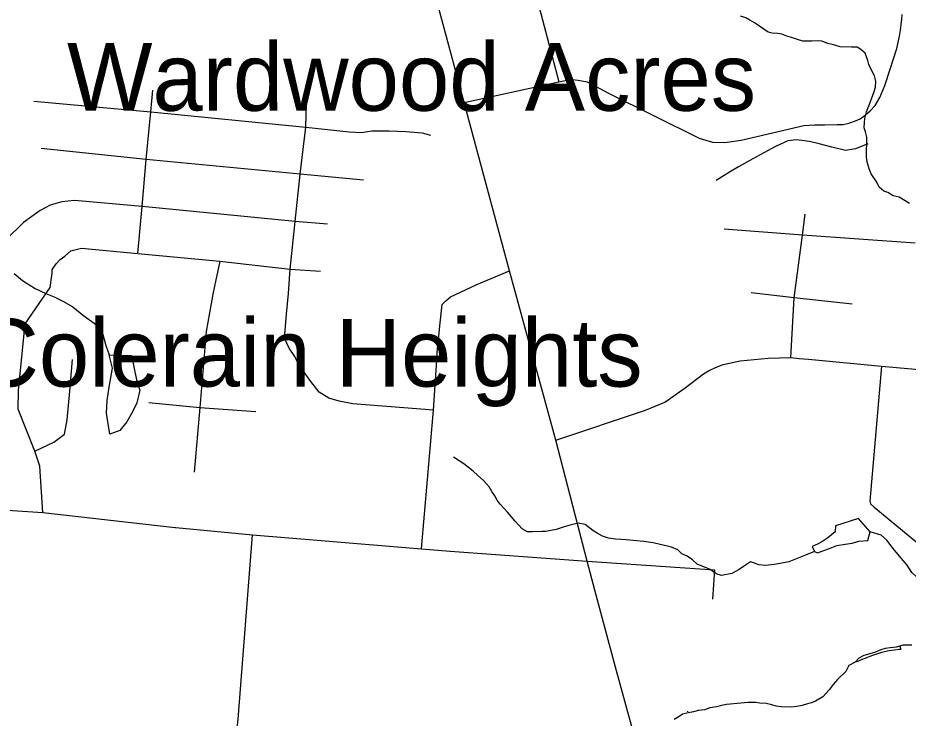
# Model space of a CAD drawing. Extents: x 0 to 34, y 0 to 22.
# Drawn here: x 3.515 to 4.554, y 16.285 to 17.102 of the extents above; entities that cross this region are included whole.
import ezdxf

# ---------------------------------------------------------------- set-up
doc = ezdxf.new("R2010")
doc.units = 0
for name, color, linetype in [('GM_X_County_Road', 7, 'Continuous'), ('GM_X_Minor_Lake', 7, 'Continuous'), ('GM_X_Minor_River', 7, 'Continuous'), ('GM_X_Township_Subdivision', 7, 'Continuous'), ('GM_X_Unincorporated_Text', 7, 'Continuous'), ('GM_X_US_Route', 7, 'Continuous')]:
    doc.layers.add(name, color=color, linetype=linetype)

msp = doc.modelspace()

# ---------------------------------------------------------------- linework, layer by layer
at = {"layer": 'GM_X_County_Road'}
for points in [[(4.1431, 16.6089), (4.2477, 16.644), (4.27, 16.6535), (4.294, 16.6701), (4.3151, 16.6862), (4.3212, 16.6898), (4.3294, 16.6938), (4.3383, 16.6974), (4.3582, 16.7015), (4.3907, 16.7048), (4.417, 16.7053), (4.427, 16.7043), (4.4376, 16.7033), (4.5229, 16.6954), (4.6194, 16.6869)], [(3.0077, 16.6072), (3.0199, 16.6034), (3.2263, 16.5685), (3.2928, 16.5595), (3.3237, 16.5541), (3.3826, 16.5464), (3.4363, 16.5348), (3.4732, 16.5304), (3.5089, 16.527), (3.5443, 16.5245), (3.6987, 16.5072), (3.6996, 16.5071)], [(3.6996, 16.5071), (3.7888, 16.4987), (3.8689, 16.4921)], [(3.6274, 15.5008), (3.6334, 15.5983), (3.6428, 15.6844), (3.6442, 15.6947), (3.6526, 15.7123), (3.6907, 15.7752), (3.6948, 15.7884), (3.6964, 15.8066), (3.7002, 15.8416), (3.7057, 15.8918), (3.7083, 15.9035), (3.7269, 15.9403), (3.7414, 15.9828), (3.7462, 16.0207), (3.7514, 16.0744), (3.7681, 16.2443), (3.7721, 16.2837), (3.7888, 16.4987)], [(3.8689, 16.4921), (3.869, 16.4921), (3.986, 16.4824), (4.0195, 16.4796), (4.1794, 16.4679)]]:
    msp.add_lwpolyline(points, dxfattribs=at)
at = {"layer": 'GM_X_Minor_Lake'}
for points in [[(3.6224, 16.6158), (3.6187, 16.6406), (3.6194, 16.6554), (3.6216, 16.6709), (3.6255, 16.6928), (3.6218, 16.7084)], [(3.6218, 16.7084), (3.6479, 16.7079), (3.6534, 16.6793), (3.6573, 16.6674), (3.6539, 16.6527), (3.6487, 16.6422), (3.6424, 16.6302), (3.6342, 16.6201), (3.6223, 16.6158)], [(4.5098, 16.5021), (4.4963, 16.5177), (4.4692, 16.5092), (4.469, 16.502), (4.4605, 16.495), (4.4532, 16.4906), (4.4482, 16.4877), (4.442, 16.4848), (4.4446, 16.479), (4.4483, 16.4774), (4.4613, 16.4821), (4.4709, 16.486), (4.4805, 16.4877), (4.4888, 16.489), (4.4965, 16.4912)], [(4.4965, 16.4912), (4.507, 16.4921), (4.5098, 16.5021)]]:
    msp.add_lwpolyline(points, dxfattribs=at)
at = {"layer": 'GM_X_Minor_River'}
for points in [[(4.5556, 16.8851), (4.5436, 16.8923), (4.5364, 16.8941), (4.5304, 16.8977), (4.5255, 16.8993), (4.5203, 16.904), (4.5175, 16.9098), (4.5109, 16.9195), (4.5084, 16.9253), (4.5063, 16.9337), (4.5053, 16.9391), (4.506, 16.9623), (4.5042, 16.9685), (4.5028, 16.9731), (4.503, 16.9795), (4.5035, 16.9841), (4.5056, 16.992), (4.5081, 16.9988), (4.5114, 17.0071), (4.5143, 17.0158), (4.5159, 17.0207), (4.5165, 17.0279), (4.5147, 17.034), (4.5104, 17.0422), (4.5083, 17.0472), (4.5072, 17.0518), (4.504, 17.0602), (4.4988, 17.0646), (4.4944, 17.0674), (4.4879, 17.0672), (4.4746, 17.0679), (4.467, 17.07), (4.4602, 17.0717), (4.4535, 17.0742), (4.4482, 17.0747), (4.4417, 17.0745), (4.4356, 17.0743), (4.431, 17.0745), (4.425, 17.0762), (4.4178, 17.0786), (4.4126, 17.0803), (4.4065, 17.0824), (4.402, 17.0833), (4.3952, 17.0838), (4.3906, 17.0847), (4.3806, 17.0919), (4.3746, 17.0958), (4.3693, 17.0987), (4.3648, 17.1014), (4.3584, 17.1035)], [(4.5057, 16.9543), (4.5072, 16.9546), (4.4926, 16.9489), (4.4808, 16.9469), (4.4649, 16.9507), (4.4502, 16.9548), (4.4388, 16.9574), (4.4237, 16.9593), (4.4138, 16.958), (4.3999, 16.9519), (4.3899, 16.9464), (4.373, 16.9373), (4.356, 16.9278), (4.3456, 16.9216), (4.3302, 16.9117)], [(3.5109, 16.8032), (3.5206, 16.7953), (3.5352, 16.7859), (3.5476, 16.7802), (3.5574, 16.7762), (3.5675, 16.771), (3.5791, 16.7646), (3.5922, 16.754), (3.6041, 16.7454), (3.6141, 16.7322), (3.6176, 16.7196), (3.6218, 16.7084)], [(4.4446, 16.479), (4.4342, 16.475), (4.4149, 16.4671), (4.4023, 16.4648), (4.3977, 16.4638), (4.3878, 16.4629), (4.3799, 16.4635), (4.3746, 16.4656), (4.3701, 16.4669), (4.3619, 16.4618), (4.3569, 16.4581), (4.3484, 16.4534), (4.3362, 16.4511), (4.3301, 16.4531), (4.323, 16.4583), (4.3174, 16.4603), (4.3125, 16.4624), (4.308, 16.4644), (4.3024, 16.4695), (4.2961, 16.4735), (4.2901, 16.4763), (4.2853, 16.481), (4.2777, 16.4843), (4.2732, 16.4852), (4.2645, 16.4873), (4.2566, 16.4891), (4.2456, 16.4909), (4.2251, 16.4926), (4.2126, 16.4934), (4.2042, 16.4947), (4.1975, 16.4972), (4.1911, 16.5004), (4.1862, 16.5036), (4.1773, 16.5107), (4.169, 16.5121), (4.1579, 16.5094), (4.1514, 16.5076), (4.1433, 16.5048), (4.1372, 16.5035), (4.1314, 16.5025), (4.1269, 16.5026), (4.1158, 16.5022), (4.1097, 16.5019), (4.1038, 16.5055), (4.0953, 16.5145), (4.0908, 16.52), (4.0864, 16.5251), (4.0779, 16.5344), (4.0743, 16.5391), (4.0717, 16.5441), (4.0684, 16.5492), (4.0652, 16.5546), (4.0585, 16.562), (4.0518, 16.5679), (4.0466, 16.573), (4.0411, 16.577), (4.0355, 16.5813), (4.0302, 16.5849), (4.0235, 16.5893)], [(4.6349, 16.4612), (4.6183, 16.4634), (4.6087, 16.4591), (4.5991, 16.4555), (4.5925, 16.4527), (4.5845, 16.4506), (4.576, 16.4482), (4.5692, 16.4495), (4.5635, 16.45), (4.5583, 16.4548), (4.5529, 16.4633), (4.5462, 16.4711), (4.5422, 16.4762), (4.5367, 16.4828), (4.5326, 16.4878), (4.5293, 16.4925), (4.5226, 16.498), (4.5097, 16.5022)], [(4.5443, 16.3688), (4.5455, 16.365), (4.543, 16.3647), (4.5382, 16.3641), (4.532, 16.3633), (4.5263, 16.3621), (4.5229, 16.3612), (4.5171, 16.3593), (4.5125, 16.3579), (4.5092, 16.3567), (4.5056, 16.3552), (4.5027, 16.354), (4.5012, 16.3536), (4.4985, 16.3524), (4.496, 16.3514), (4.4935, 16.3505), (4.4921, 16.3499)], [(4.54, 16.3677), (4.5331, 16.3667), (4.5274, 16.3661), (4.5221, 16.3644), (4.5147, 16.3612), (4.5025, 16.3577), (4.4967, 16.3548), (4.4921, 16.3499)], [(4.5443, 16.3688), (4.54, 16.3677)], [(4.5583, 16.3698), (4.553, 16.37), (4.5477, 16.3698), (4.5443, 16.3688)], [(4.4921, 16.3499), (4.4847, 16.346), (4.4814, 16.3392), (4.4717, 16.33), (4.4666, 16.324), (4.4618, 16.3177), (4.4544, 16.3095), (4.4459, 16.3044), (4.4413, 16.3027), (4.4367, 16.3013), (4.4305, 16.2995), (4.424, 16.2982), (4.4183, 16.2976), (4.4058, 16.2979), (4.4001, 16.2989), (4.3948, 16.3001), (4.3884, 16.3018), (4.3808, 16.3024), (4.3759, 16.303), (4.3675, 16.3032), (4.3587, 16.3023), (4.342, 16.3005), (4.3362, 16.2995), (4.3305, 16.2978), (4.3228, 16.2968), (4.3163, 16.2943), (4.3095, 16.2938), (4.3037, 16.292), (4.2957, 16.2907), (4.2913, 16.2894)], [(4.2965, 16.293), (4.2966, 16.2923)], [(4.2917, 16.2899), (4.2868, 16.2868), (4.281, 16.2831)]]:
    msp.add_lwpolyline(points, dxfattribs=at)
at = {"layer": 'GM_X_Township_Subdivision'}
for points in [[(4.2504, 17.246), (4.2399, 17.2463), (4.2209, 17.2479), (4.2, 17.2504), (4.1444, 17.2619), (4.1342, 17.2617), (4.1233, 17.2587), (4.1133, 17.2519), (4.1072, 17.2448), (4.1016, 17.2378), (4.098, 17.2281), (4.0972, 17.2166), (4.1007, 17.2009), (4.1059, 17.1806), (4.1093, 17.1652), (4.1138, 17.1512), (4.1464, 17.0268)], [(4.5267, 17.0228), (4.5332, 17.0419), (4.5407, 17.066), (4.5441, 17.0801), (4.5451, 17.0873), (4.5458, 17.0934), (4.5465, 17.0999), (4.5469, 17.1055)], [(4.0359, 17.0028), (4.1464, 17.0268), (4.1519, 17.0281)], [(4.1519, 17.0281), (4.1588, 17.0296), (4.162, 17.0296), (4.1688, 17.0289), (4.1794, 17.0268), (4.1835, 17.0251), (4.2044, 17.0136), (4.31, 16.9611), (4.3256, 16.9565), (4.3403, 16.9561), (4.3591, 16.9591), (4.4325, 16.9761), (4.4446, 16.9767), (4.4568, 16.9769), (4.4711, 16.9771), (4.4782, 16.9773), (4.4849, 16.9788), (4.4925, 16.9813), (4.498, 16.9837), (4.5039, 16.9882), (4.5096, 16.993), (4.5154, 16.9992), (4.5212, 17.0085), (4.5267, 17.0228)], [(3.6551, 16.8268), (3.6602, 16.8815), (3.6648, 16.9362), (3.6704, 16.9918), (3.6728, 17.0173)], [(3.5337, 17.0043), (3.6704, 16.9918), (3.851, 16.9739), (3.9019, 16.9687), (3.9161, 16.9677), (3.9282, 16.9699), (3.9484, 16.9699), (3.968, 16.969), (3.9869, 16.9674), (3.9965, 16.9649)], [(4.0003, 16.6438), (3.9059, 16.6515), (3.8901, 16.6543), (3.878, 16.658), (3.8668, 16.6649), (3.8569, 16.6776), (3.8426, 16.6978), (3.8383, 16.7064), (3.8317, 16.7164), (3.8261, 16.7279), (3.8274, 16.7415), (3.8286, 16.7561), (3.8308, 16.78), (3.8327, 16.8085), (3.8386, 16.8639), (3.8445, 16.9193), (3.851, 16.9739), (3.8519, 17.0009)], [(3.9186, 16.9122), (3.8445, 16.9193), (3.6648, 16.9362), (3.5425, 16.9491)], [(3.8766, 16.8608), (3.8386, 16.8639), (3.6602, 16.8815), (3.5812, 16.8884), (3.5665, 16.887), (3.553, 16.8832), (3.541, 16.877), (3.5216, 16.8628), (3.4605, 16.8035), (3.4221, 16.7604), (3.3897, 16.7285), (3.3838, 16.7214), (3.3793, 16.711), (3.3779, 16.6956), (3.3748, 16.6696), (3.3712, 16.6447), (3.371, 16.6339), (3.3731, 16.6233), (3.3815, 16.607), (3.3861, 16.5965), (3.388, 16.5857), (3.3826, 16.5464)], [(4.417, 16.7053), (4.421, 16.7752), (4.4308, 16.8481), (4.434, 16.8724)], [(4.5621, 16.8386), (4.4308, 16.8481), (4.3393, 16.855)], [(3.5546, 16.8011), (3.555, 16.8037), (3.5553, 16.8076), (3.5562, 16.8098), (3.5597, 16.8147), (3.5644, 16.8199), (3.5698, 16.8235), (3.5769, 16.8299), (3.5893, 16.833), (3.6551, 16.8268), (3.7507, 16.8176), (3.8327, 16.8085), (3.8684, 16.8061)], [(3.7507, 16.8176), (3.7446, 16.7885)], [(4.0044, 16.7081), (4.0046, 16.7116), (4.0079, 16.7459), (4.0104, 16.7671), (4.0145, 16.7716), (4.02, 16.7762), (4.0507, 16.7906), (4.0889, 16.8066)], [(3.5443, 16.5245), (3.5409, 16.5785), (3.535, 16.5962), (3.5154, 16.6452), (3.5157, 16.6673), (3.5235, 16.7448), (3.5527, 16.787), (3.5546, 16.8011)], [(3.7446, 16.7885), (3.7426, 16.7791), (3.7348, 16.7357), (3.7274, 16.6472), (3.7209, 16.5715)], [(4.4889, 16.7676), (4.421, 16.7752), (4.3708, 16.7808)], [(3.986, 16.4824), (4.0003, 16.6438), (4.0044, 16.7081)], [(3.535, 16.5962), (3.557, 16.6066), (3.5697, 16.6161), (3.5728, 16.6328), (3.5756, 16.6663), (3.5787, 16.703)], [(4.5229, 16.6954), (4.5093, 16.5377), (4.51, 16.5346), (4.514, 16.5314), (4.5654, 16.4888), (4.5695, 16.486), (4.5759, 16.4851), (4.6004, 16.488), (4.6411, 16.4852), (4.6505, 16.4838)], [(3.6678, 16.6528), (3.7274, 16.6472), (3.7929, 16.6423)], [(4.1794, 16.4679), (4.3279, 16.4578), (4.3259, 16.4234)]]:
    msp.add_lwpolyline(points, dxfattribs=at)
at = {"layer": 'GM_X_US_Route'}
msp.add_lwpolyline([(4.347, 15.8571), (4.343, 15.8718), (4.3094, 15.9915), (4.3082, 15.9958), (4.2961, 16.0399), (4.2826, 16.089), (4.2509, 16.204), (4.2124, 16.3441), (4.1884, 16.4342), (4.1794, 16.4679), (4.1431, 16.6089), (4.0889, 16.8066), (4.0359, 17.0028), (4.0043, 17.1198), (3.9604, 17.2824), (3.9324, 17.3858)], dxfattribs=at)

# ---------------------------------------------------------------- texts
at = {"layer": 'GM_X_Unincorporated_Text'}
for s, p in [('Wardwood Acres', (3.5725, 16.9932)), ('Colerain Heights', (3.4634, 16.6715))]:
    msp.add_text(s, height=0.078977, rotation=0, dxfattribs=at).set_placement(p)

doc.saveas('drawing.dxf')
